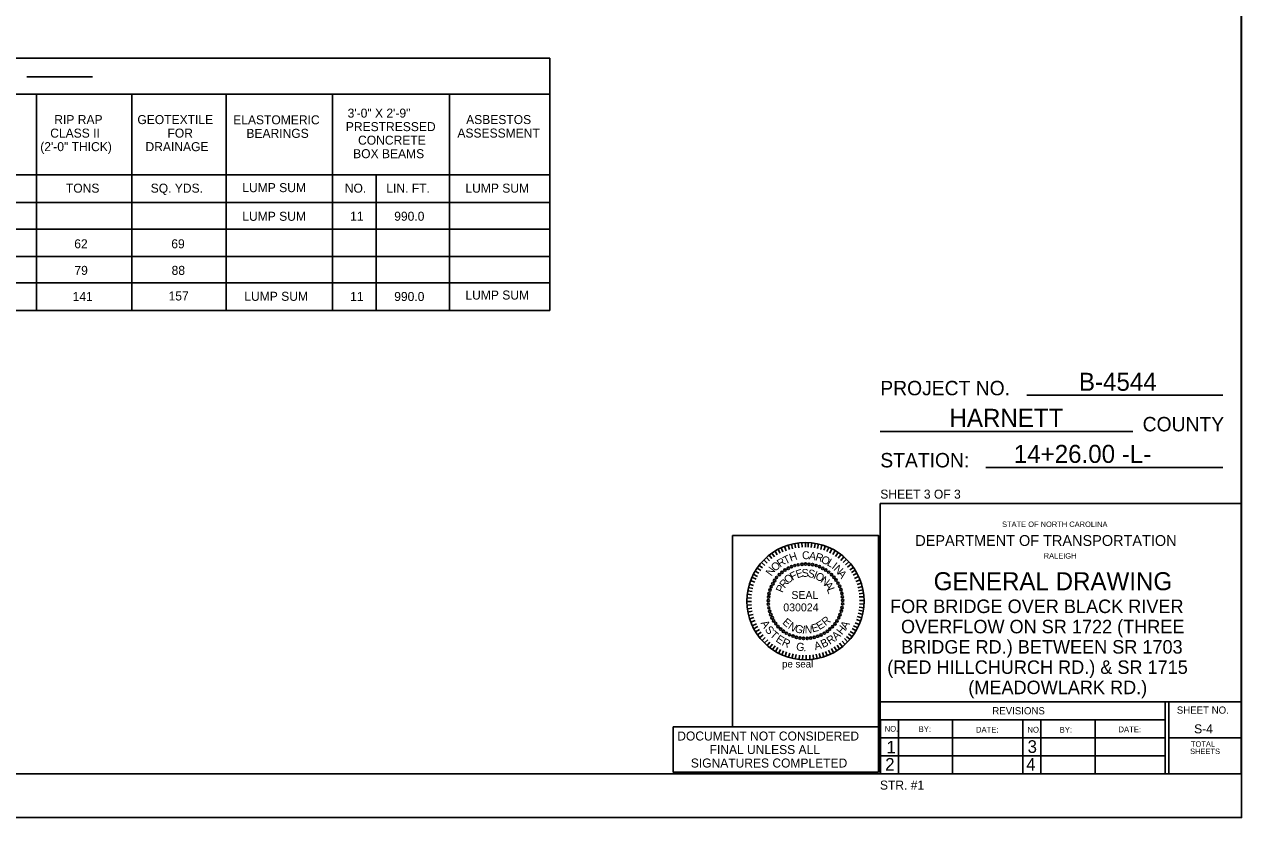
# Model space of a CAD drawing. Extents: x -20 to 509, y -659 to 21.
# Drawn here: x 239.1 to 509.1, y -658.9 to -482.9 of the extents above; entities that cross this region are included whole.
import ezdxf

# ---------------------------------------------------------------- set-up
doc = ezdxf.new("R2010")
doc.units = 0
for name, color, linetype in [('Default', 7, 'Continuous'), ('Peseal', 7, 'Continuous'), ('Plan Sheet CELL', 7, 'Continuous'), ('Plot Shape CELL', 7, 'Continuous'), ('Sheet Sticker Exception Certification CELL', 7, 'Continuous'), ('Subtitle Text', 7, 'Continuous'), ('Text', 7, 'Continuous'), ('Title Text', 7, 'Continuous'), ('Typical Text General CELL', 7, 'Continuous'), ('User Information Notes', 7, 'Continuous'), ('User Information Notes CELL', 7, 'Continuous')]:
    doc.layers.add(name, color=color, linetype=linetype)

msp = doc.modelspace()

# ---------------------------------------------------------------- linework, layer by layer
at = {"layer": 'Default'}
for p, q in [((355.63, -490.36), (49.55, -490.36)), ((265.45, -490.36), (193.73, -490.36)), ((355.63, -546.38), (355.63, -490.36)), ((254.23, -494.54), (239.64, -494.54)), ((274.98, -498.35), (49.55, -498.35)), ((338.29, -498.35), (198.01, -498.35)), ((241.39, -498.35), (313.11, -498.35)), ((283.83, -498.35), (283.83, -546.38)), ((355.63, -498.35), (286.49, -498.35)), ((49.55, -516.28), (274.98, -516.28)), ((139.48, -516.28), (355.63, -516.28)), ((49.55, -546.38), (355.63, -546.38))]:
    msp.add_line(p, q, dxfattribs=at)
at = {"layer": 'Peseal'}
for p, q in [((407.33, -599.9), (406.96, -599.03)), ((408.08, -599.65), (407.71, -598.72)), ((408.77, -599.4), (408.46, -598.4)), ((409.46, -599.22), (409.21, -598.22)), ((410.15, -599.03), (409.96, -598.03)), ((410.83, -598.97), (410.71, -597.97)), ((411.58, -598.84), (411.52, -597.84)), ((412.33, -598.84), (412.33, -597.84)), ((412.9, -598.84), (412.96, -597.84)), ((413.58, -598.9), (413.71, -597.9)), ((414.33, -599.03), (414.46, -598.03)), ((415.02, -599.15), (415.21, -598.15)), ((415.71, -599.34), (415.96, -598.34)), ((416.4, -599.53), (416.77, -598.59)), ((417.08, -599.84), (417.52, -598.9)), ((417.77, -600.15), (418.21, -599.22)), ((403.83, -602.4), (403.08, -601.65)), ((404.33, -601.9), (403.71, -601.15)), ((404.9, -601.4), (404.27, -600.65)), ((405.46, -600.97), (404.9, -600.15)), ((406.08, -600.59), (405.58, -599.72)), ((406.71, -600.22), (406.27, -599.34)), ((418.4, -600.47), (418.9, -599.59)), ((419.02, -600.9), (419.58, -600.03)), ((419.58, -601.28), (420.21, -600.53)), ((420.21, -601.78), (420.83, -601.03)), ((420.71, -602.22), (421.4, -601.53)), ((402.02, -604.65), (401.15, -604.15)), ((402.46, -604.03), (401.58, -603.47)), ((402.83, -603.47), (402.08, -602.9)), ((403.33, -602.9), (402.58, -602.28)), ((421.21, -602.78), (421.96, -602.09)), ((421.65, -603.28), (422.46, -602.65)), ((422.15, -603.9), (422.96, -603.34)), ((422.52, -604.47), (423.33, -603.97)), ((422.9, -605.09), (423.77, -604.65)), ((400.83, -607.34), (399.9, -607.03)), ((401.08, -606.65), (400.15, -606.28)), ((401.4, -605.97), (400.46, -605.53)), ((401.71, -605.34), (400.77, -604.84)), ((423.21, -605.78), (424.08, -605.34)), ((423.52, -606.47), (424.46, -606.09)), ((423.77, -607.15), (424.71, -606.84)), ((400.33, -610.15), (399.33, -610.09)), ((400.4, -609.4), (399.46, -609.28)), ((400.52, -608.72), (399.52, -608.53)), ((400.65, -608.03), (399.71, -607.78)), ((423.96, -607.84), (424.9, -607.59)), ((424.08, -608.53), (425.08, -608.34)), ((424.21, -609.22), (425.21, -609.09)), ((424.27, -609.9), (425.27, -609.84)), ((400.33, -610.9), (399.33, -610.9)), ((400.33, -611.65), (399.33, -611.72)), ((400.46, -612.4), (399.46, -612.53)), ((424.27, -612.15), (425.27, -612.28)), ((424.33, -610.65), (425.33, -610.65)), ((424.33, -611.4), (425.33, -611.47)), ((400.52, -613.09), (399.58, -613.28)), ((400.71, -613.78), (399.71, -614.03)), ((400.9, -614.47), (399.96, -614.78)), ((401.15, -615.15), (400.21, -615.53)), ((423.65, -614.9), (424.58, -615.28)), ((423.83, -614.22), (424.83, -614.53)), ((424.02, -613.53), (425.02, -613.78)), ((424.15, -612.84), (425.15, -613.03)), ((401.46, -615.84), (400.52, -616.28)), ((401.77, -616.47), (400.83, -616.97)), ((402.15, -617.15), (401.27, -617.65)), ((402.52, -617.72), (401.71, -618.28)), ((421.9, -618.09), (422.71, -618.72)), ((422.27, -617.53), (423.15, -618.09)), ((422.71, -616.9), (423.58, -617.4)), ((423.02, -616.28), (423.96, -616.72)), ((423.33, -615.65), (424.27, -616.03)), ((402.96, -618.34), (402.15, -618.97)), ((403.4, -618.9), (402.71, -619.53)), ((403.96, -619.4), (403.21, -620.15)), ((404.46, -619.9), (403.83, -620.65)), ((405.02, -620.4), (404.46, -621.15)), ((405.58, -620.78), (405.02, -621.59)), ((419.33, -620.59), (419.9, -621.4)), ((419.9, -620.15), (420.52, -620.97)), ((420.46, -619.72), (421.08, -620.4)), ((420.96, -619.15), (421.71, -619.9)), ((421.46, -618.65), (422.21, -619.34)), ((406.21, -621.15), (405.71, -622.03)), ((406.83, -621.53), (406.4, -622.4)), ((407.46, -621.84), (407.08, -622.72)), ((408.15, -622.09), (407.83, -623.03)), ((408.9, -622.34), (408.58, -623.28)), ((409.58, -622.53), (409.33, -623.47)), ((410.27, -622.65), (410.08, -623.65)), ((411.02, -622.78), (410.9, -623.78)), ((411.77, -622.84), (411.71, -623.84)), ((412.52, -622.84), (412.52, -623.84)), ((413.27, -622.78), (413.33, -623.78)), ((414.02, -622.72), (414.15, -623.72)), ((414.71, -622.59), (414.9, -623.59)), ((415.4, -622.47), (415.65, -623.4)), ((416.08, -622.22), (416.4, -623.22)), ((416.77, -621.97), (417.15, -622.9)), ((417.46, -621.72), (417.9, -622.59)), ((418.08, -621.34), (418.58, -622.28)), ((418.71, -620.97), (419.27, -621.84))]:
    msp.add_line(p, q, dxfattribs=at)
for centre, radius in [((406.52, -604.97), 0.265), ((407.12, -604.43), 0.269), ((407.8, -603.93), 0.269), ((408.52, -603.53), 0.28), ((409.24, -603.18), 0.238), ((409.96, -602.93), 0.228), ((410.74, -602.75), 0.221), ((411.55, -602.65), 0.252), ((412.33, -602.59), 0.25), ((413.12, -602.65), 0.252), ((413.9, -602.72), 0.258), ((414.71, -602.93), 0.228), ((415.43, -603.18), 0.238), ((416.15, -603.56), 0.252), ((416.83, -603.93), 0.252), ((417.49, -604.4), 0.244), ((418.12, -604.97), 0.244), ((404.74, -607.62), 0.238), ((405.12, -606.97), 0.288), ((405.49, -606.25), 0.269), ((405.93, -605.56), 0.221), ((418.65, -605.56), 0.244), ((419.12, -606.15), 0.252), ((419.55, -606.84), 0.252), ((419.93, -607.56), 0.238), ((404.15, -609.93), 0.252), ((404.27, -609.15), 0.258), ((404.46, -608.37), 0.267), ((420.21, -608.31), 0.267), ((420.4, -609.09), 0.258), ((420.52, -609.87), 0.252), ((404.08, -610.72), 0.25), ((404.08, -611.5), 0.252), ((404.21, -612.31), 0.252), ((420.27, -613.03), 0.258), ((420.46, -612.25), 0.252), ((420.58, -610.65), 0.25), ((420.58, -611.43), 0.252), ((404.4, -613.09), 0.258), ((404.65, -613.81), 0.267), ((404.96, -614.53), 0.28), ((405.3, -615.22), 0.252), ((419.3, -615.22), 0.252), ((419.74, -614.47), 0.252), ((420.02, -613.81), 0.267), ((405.77, -615.81), 0.244), ((406.27, -616.47), 0.265), ((406.83, -617.03), 0.265), ((407.43, -617.5), 0.269), ((408.08, -617.93), 0.252), ((408.8, -618.31), 0.238), ((415.77, -618.34), 0.28), ((416.52, -617.93), 0.252), ((417.18, -617.53), 0.244), ((417.74, -617.03), 0.244), ((418.33, -616.5), 0.244), ((418.87, -615.87), 0.269), ((409.55, -618.59), 0.267), ((410.33, -618.84), 0.258), ((411.12, -619.03), 0.252), ((411.9, -619.09), 0.25), ((412.71, -619.09), 0.25), ((413.49, -619.03), 0.252), ((414.27, -618.84), 0.258), ((415.05, -618.62), 0.238)]:
    msp.add_circle(centre, radius, dxfattribs=at)
at = {"layer": 'Plan Sheet CELL'}
for p, q in [((508.93, -313.17), (508.93, -649.17)), ((504.93, -565.16), (461.46, -565.16)), ((484.93, -573.16), (428.93, -573.16)), ((504.93, -581.16), (452.3, -581.16)), ((508.93, -589.16), (428.93, -589.16)), ((428.93, -589.16), (428.93, -649.17)), ((428.93, -633.16), (508.93, -633.16)), ((492.13, -633.16), (492.13, -649.17)), ((492.93, -633.16), (492.93, -649.17)), ((428.93, -637.16), (492.16, -637.16)), ((428.98, -637.16), (428.98, -649.17)), ((432.93, -637.16), (432.93, -649.17)), ((444.93, -637.23), (444.93, -649.23)), ((460.54, -637.16), (460.54, -649.27)), ((464.55, -637.16), (464.55, -649.18)), ((476.55, -637.16), (476.55, -649.18)), ((428.93, -641.16), (492.29, -641.16)), ((492.93, -641.16), (508.79, -641.16)), ((428.93, -645.16), (492.16, -645.16)), ((-3.08, -649.17), (508.93, -649.17)), ((509.07, -658.86), (509.07, -658.86))]:
    msp.add_line(p, q, dxfattribs=at)
at = {"layer": 'Plot Shape CELL'}
msp.add_lwpolyline([(-19.94, -306.87), (509.07, -306.87), (509.07, -658.86), (-19.94, -658.86)], close=True, dxfattribs=at)
at = {"layer": 'Sheet Sticker Exception Certification CELL'}
msp.add_lwpolyline([(382.96, -638.73), (428.53, -638.73), (428.53, -648.77), (382.96, -648.77)], close=True, dxfattribs=at)
at = {"layer": 'Typical Text General CELL'}
for p, q in [((241.79, -498.35), (241.79, -546.38)), ((241.79, -498.35), (241.79, -546.38)), ((262.97, -498.35), (262.97, -546.38)), ((307.43, -498.35), (307.43, -546.38)), ((333.39, -498.35), (333.39, -546.38)), ((317.09, -516.28), (317.09, -546.38)), ((49.55, -522.4), (274.98, -522.4)), ((139.48, -522.4), (355.63, -522.4)), ((49.55, -528.33), (274.98, -528.33)), ((139.48, -528.33), (355.63, -528.33)), ((49.55, -534.39), (355.63, -534.39)), ((49.55, -540.19), (274.98, -540.19)), ((139.48, -540.19), (355.63, -540.19))]:
    msp.add_line(p, q, dxfattribs=at)
at = {"layer": 'User Information Notes'}
msp.add_line((412.33, -610.84), (412.33, -610.84), dxfattribs=at)
at = {"layer": 'User Information Notes CELL'}
msp.add_line((412.33, -610.84), (412.33, -610.84), dxfattribs=at)
msp.add_lwpolyline([(396.13, -596.24), (428.53, -596.24), (428.53, -638.73), (396.13, -638.73)], close=True, dxfattribs=at)
msp.add_circle((412.33, -610.84), 13, dxfattribs=at)

# ---------------------------------------------------------------- texts
at = {"layer": 'Default'}
for s, p in [('3\'-0" X 2\'-9"', (310.8, -503.56)), ('RIP RAP', (245.75, -505)), ('GEOTEXTILE', (264.17, -505)), ('ELASTOMERIC', (285.42, -505.05)), ('PRESTRESSED', (310.4, -506.56)), ('ASBESTOS', (337.08, -504.99)), ('CLASS II', (244.84, -508)), ('FOR ', (270.84, -508)), ('BEARINGS', (288.35, -508.05)), ('CONCRETE', (313.11, -509.56)), ('ASSESSMENT', (335.14, -507.99)), ('(2\'-0" THICK)', (242.63, -511)), ('DRAINAGE', (265.97, -511)), ('BOX BEAMS', (312.02, -512.56)), ('TONS', (248.32, -520.21)), ('SQ. YDS.', (267.12, -520.21)), ('LUMP SUM', (287.44, -520.09)), ('NO.', (310.17, -520.21)), ('LIN. FT.', (319.38, -520.21)), ('LUMP SUM', (336.92, -520.21)), ('LUMP SUM', (287.44, -526.45)), ('LUMP SUM', (287.89, -544.2)), ('LUMP SUM', (336.92, -543.92))]:
    msp.add_text(s, height=2, dxfattribs=at).set_placement(p)
at = {"layer": 'Peseal'}
for s, height, rotation, p in [('R', 1.75, 32.9699, (406.71, -603.4)), ('T', 1.75, 25.943, (407.9, -602.72)), ('H', 1.75, 18.9162, (409.08, -602.09)), ('C', 1.75, 4.8625, (411.65, -601.59)), ('A', 1.75, 350.8088, (413.02, -601.53)), ('R', 1.75, 343.7819, (414.4, -601.72)), ('O', 1.75, 336.7551, (415.65, -602.22)), ('L', 1.75, 329.7282, (416.96, -602.78)), ('N', 1.75, 54.0504, (404.77, -605.4)), ('O', 1.75, 39.9967, (405.58, -604.34)), ('F', 1.75, 26.4777, (409.4, -606.28)), ('E', 1.75, 18.4448, (410.52, -605.78)), ('S', 1.75, 2.3789, (411.52, -605.47)), ('S', 1.75, 346.313, (412.71, -605.4)), ('I', 1.75, 338.28, (413.96, -605.72)), ('O', 1.75, 330.2471, (414.33, -605.78)), ('I', 1.75, 322.7014, (418.02, -603.47)), ('N', 1.75, 315.6745, (418.46, -603.84)), ('A', 1.75, 308.6477, (419.33, -604.78)), ('P', 1.75, 66.6424, (407.27, -609.09)), ('R', 1.75, 50.5765, (407.71, -608.09)), ('O', 1.75, 42.5436, (408.52, -607.09)), ('N', 1.75, 322.2141, (415.52, -606.53)), ('A', 1.75, 306.1483, (416.4, -607.28)), ('L', 1.75, 290.0824, (417.02, -608.15)), ('A', 1.77, 300.3993, (402.34, -615.69)), ('E', 1.75, 318.5179, (407.08, -615.72)), ('N', 1.75, 326.5361, (408.33, -616.78)), ('E', 1.75, 30.6815, (415.4, -617.28)), ('R', 1.75, 38.6997, (416.77, -616.4)), ('A', 1.77, 59.6007, (421.45, -617.2)), ('S', 1.77, 309.4349, (403.22, -617.2)), ('T', 1.77, 318.1096, (404.29, -618.5)), ('G', 1.75, 342.5725, (409.83, -617.59)), ('I', 1.75, 350.5906, (411.52, -617.97)), ('N', 1.75, 358.6088, (412.15, -617.97)), ('E', 1.75, 14.6452, (413.9, -617.78)), ('A', 1.77, 42.3241, (419.15, -619.62)), ('H', 1.77, 51.3597, (420.44, -618.44)), ('E', 1.77, 327.1453, (405.59, -619.67)), ('R', 1.78, 335.458, (406.94, -620.55)), ('G', 1.77, 353.3858, (410.19, -621.74)), ('A', 1.77, 15.7955, (414.51, -621.74)), ('B', 1.77, 24.8312, (416.19, -621.26)), ('R', 1.77, 33.5776, (417.73, -620.55)), ('.', 1.77, 2.1323, (411.87, -621.94))]:
    msp.add_text(s, height=height, rotation=rotation, dxfattribs=at).set_placement(p)
for s, p in [('SEAL', (409.21, -610.34)), ('030024', (407.42, -613.09))]:
    msp.add_text(s, height=1.75, dxfattribs=at).set_placement(p)
at = {"layer": 'Plan Sheet CELL'}
for s, height, p in [('PROJECT NO.', 3.2, (428.93, -565.16)), ('COUNTY', 3.2, (487.11, -573.16)), ('STATION:', 3.2, (428.93, -581.16)), ('SHEET 3 OF 3', 2, (428.93, -588.09)), ('STATE OF NORTH CAROLINA', 1.1999, (455.93, -594.37)), ('DEPARTMENT OF TRANSPORTATION', 2.3999, (436.69, -598.58)), ('RALEIGH', 1.2, (465.17, -601.39)), ('REVISIONS', 1.6, (453.77, -635.95)), ('SHEET NO.', 1.6, (494.69, -635.8)), ('NO.', 1.275, (429.88, -639.79)), ('BY:', 1.275, (437.43, -639.85)), ('DATE:', 1.275, (450.14, -639.99)), ('NO.', 1.275, (461.56, -639.99)), ('BY:', 1.275, (468.71, -640)), ('DATE:', 1.275, (481.75, -639.92)), ('1', 2.8, (430.3, -644.62)), ('3', 2.8, (461.59, -644.49)), ('TOTAL', 1.2, (497.83, -643.13)), ('SHEETS', 1.2, (497.64, -644.75)), ('2', 2.8, (430.01, -648.43)), ('4', 2.8, (461.29, -648.43))]:
    msp.add_text(s, height=height, dxfattribs=at).set_placement(p)
at = {"layer": 'Sheet Sticker Exception Certification CELL'}
for s, p in [('DOCUMENT NOT CONSIDERED', (383.9, -641.75)), ('FINAL UNLESS ALL', (391.07, -644.75)), ('SIGNATURES COMPLETED', (386.91, -647.74))]:
    msp.add_text(s, height=1.9955, dxfattribs=at).set_placement(p)
at = {"layer": 'Subtitle Text'}
for s, p in [('FOR BRIDGE OVER BLACK RIVER', (431.09, -613.47)), ('OVERFLOW ON SR 1722 (THREE', (433.52, -617.97)), ('BRIDGE RD.) BETWEEN SR 1703', (433.56, -622.47)), ('(RED HILLCHURCH RD.) & SR 1715', (430.47, -626.97)), ('(MEADOWLARK RD.)', (448.45, -631.47))]:
    msp.add_text(s, height=3, dxfattribs=at).set_placement(p)
at = {"layer": 'Text'}
for s, p in [('11', (311.35, -526.44)), ('990.0', (321.13, -526.44)), ('62', (250.17, -532.55)), ('69', (271.69, -532.55)), ('79', (250.21, -538.45)), ('88', (271.76, -538.45)), ('141', (249.81, -544.24)), ('157', (271.09, -544.13)), ('11', (311.35, -544.24)), ('990.0', (321.13, -544.24)), ('S-4', (498.53, -640.16)), ('STR. #1', (428.85, -652.64))]:
    msp.add_text(s, height=2, dxfattribs=at).set_placement(p)
at = {"layer": 'Title Text'}
for s, p in [('B-4544', (472.98, -564.16)), ('HARNETT', (444.27, -572.16)), ('14+26.00 -L-', (458.54, -580.16)), ('GENERAL DRAWING', (440.76, -608.41))]:
    msp.add_text(s, height=4, dxfattribs=at).set_placement(p)
at = {"layer": 'User Information Notes CELL'}
msp.add_text('pe seal', height=1.6, dxfattribs=at).set_placement((407.15, -625.55))

doc.saveas('drawing.dxf')
